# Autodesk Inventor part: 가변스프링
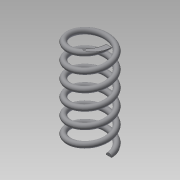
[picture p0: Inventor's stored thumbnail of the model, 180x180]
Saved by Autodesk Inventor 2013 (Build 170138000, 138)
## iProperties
Created: 2020-02
Part Number: 가변스프링
Material: 일반
Document SubType Name: Modeling
Designer: Administrator
Density: 1 g/cm^3
Author: Administrator
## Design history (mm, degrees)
sketch "스케치1"
  geometry: L1 (0, 0)-(7, 0); L2 (7, 0)-(7, -35.5); L3 (7, -35.5)-(0, -35.5); L4 (0, -35.5)-(0, 0); C1 r 1 at (7, 0)
  constraints: 8 end point, 2 parallel, 1 centre point, 1 coincident, 1 horizontal, 1 perpendicular
  dimensions: "d0" = 2 diameter of C1; "d2" = 35.5 distance of L1.end L2.end (derived); "d3" = 14 diameter of L2 L4
feature "코일1" sketch "스케치1" pitch "d4" = 10; turns "d6" = 6; dims "d5" = 35.5 (= d2), "d7" = 0, angle "d8" = 90 deg, angle "d9" = 90 deg, "d10" = 0, "d11" = 0
sketch "스케치2"
  geometry: L1 (-35.5, 10)-(0, 10); L2 (0, 10)-(0, -10); L3 (0, -10)-(-35.5, -10); L4 (-35.5, -10)-(-35.5, 10); 2 further points
  constraints: 8 end point, 2 parallel, 1 coincident, 1 horizontal, 1 midpoint, 1 perpendicular
  dimensions: "d12" = 35.5 distance of L2.end L3.end (derived); "d14" = 20 distance of L3.end L1.start
extrude "돌출1" sketch "스케치2" stored distance "d15" = 20; taper "d16" = 0 deg
node "솔리드1"
